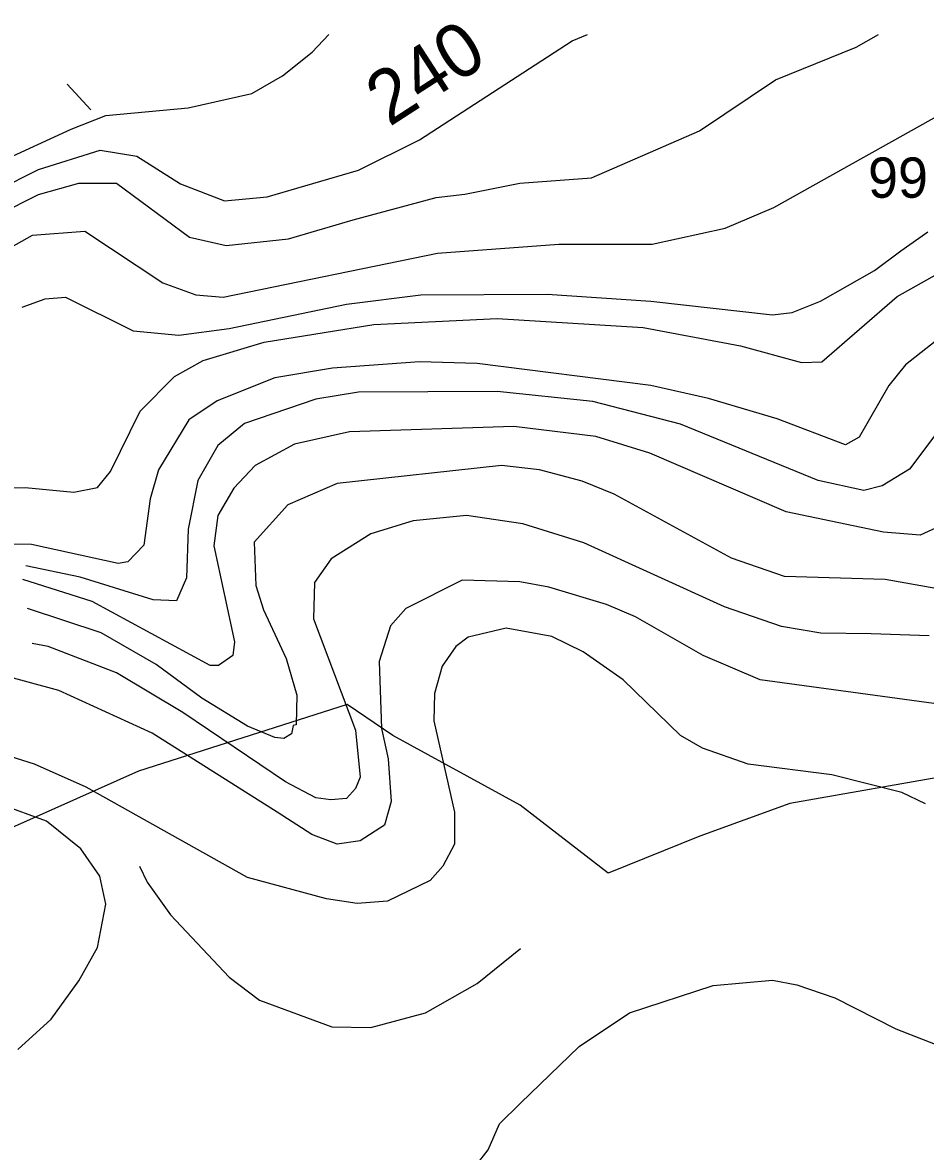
# Model space of a CAD drawing. Extents: x -662500 to -653478, y -1056827 to -1049993.
# Drawn here: x -661381.2 to -661213, y -1051221.5 to -1051011.2 of the extents above; entities that cross this region are included whole.
import ezdxf

# ---------------------------------------------------------------- set-up
doc = ezdxf.new("R2010")
doc.units = 0
doc.layers.add('Vrstva 24', color=7, linetype='Continuous')
doc.layers.add('Vrstva 7', color=7, linetype='Continuous')

msp = doc.modelspace()

# ---------------------------------------------------------------- linework, layer by layer
at = {"layer": 'Vrstva 24'}
msp.add_lwpolyline([(-661207.17, -1051151.19), (-661238.28, -1051156.7), (-661255.08, -1051162.76), (-661272.15, -1051169.64), (-661288.53, -1051156.97), (-661312.21, -1051144.03), (-661320.75, -1051138.25), (-661359.57, -1051150.64), (-661432.95, -1051183.41)], dxfattribs=at)
at = {"layer": 'Vrstva 7'}
for p, q in [((-661327.26, -1051016.72), (-661324.12, -1051013.4)), ((-661278.83, -1051014.6), (-661275.99, -1051013.4)), ((-661225.93, -1051015.73), (-661221.8, -1051013.4)), ((-661307.28, -1051033.02), (-661278.83, -1051014.6)), ((-661332.79, -1051021.12), (-661327.26, -1051016.72)), ((-661240.96, -1051021.83), (-661225.93, -1051015.73)), ((-661338.46, -1051024.38), (-661332.79, -1051021.12)), ((-661255.13, -1051031.32), (-661240.96, -1051021.83)), ((-661368.47, -1051027.44), (-661372.89, -1051022.68)), ((-661350.36, -1051027.07), (-661338.46, -1051024.38)), ((-661241.24, -1051045.63), (-661204.82, -1051025.23)), ((-661365.67, -1051028.51), (-661350.36, -1051027.07)), ((-661372.13, -1051031.03), (-661365.67, -1051028.51)), ((-661385.41, -1051037.13), (-661372.13, -1051031.03)), ((-661275.25, -1051040.11), (-661255.13, -1051031.32)), ((-661318.62, -1051038.69), (-661307.28, -1051033.02)), ((-661378.23, -1051038.56), (-661366.75, -1051034.98)), ((-661366.75, -1051034.98), (-661359.93, -1051036.05)), ((-661359.93, -1051036.05), (-661351.78, -1051041.24)), ((-661389.71, -1051044.31), (-661378.23, -1051038.56)), ((-661335.62, -1051043.65), (-661318.62, -1051038.69)), ((-661288.57, -1051041.1), (-661275.25, -1051040.11)), ((-661378.23, -1051043.23), (-661370.7, -1051041.08)), ((-661370.7, -1051041.08), (-661363.68, -1051041.1)), ((-661363.68, -1051041.1), (-661350.08, -1051051.16)), ((-661351.78, -1051041.24), (-661343.56, -1051044.36)), ((-661298.83, -1051043.16), (-661288.57, -1051041.1)), ((-661385.41, -1051046.82), (-661378.23, -1051043.23)), ((-661343.56, -1051044.36), (-661335.62, -1051043.65)), ((-661319.61, -1051047.9), (-661304.16, -1051043.79)), ((-661304.16, -1051043.79), (-661298.83, -1051043.16)), ((-661250.31, -1051049.46), (-661241.24, -1051045.63)), ((-661331.65, -1051051.45), (-661319.61, -1051047.9)), ((-661389, -1051056.15), (-661379.31, -1051050.77)), ((-661379.31, -1051050.77), (-661369.62, -1051050.05)), ((-661369.62, -1051050.05), (-661355.04, -1051059.66)), ((-661350.08, -1051051.16), (-661343.28, -1051052.72)), ((-661263.91, -1051052.44), (-661250.31, -1051049.46)), ((-661217.64, -1051053.69), (-661212.61, -1051050.17)), ((-661343.28, -1051052.72), (-661331.65, -1051051.45)), ((-661303.88, -1051054.14), (-661281.34, -1051052.44)), ((-661281.34, -1051052.44), (-661263.91, -1051052.44)), ((-661343.84, -1051062.36), (-661303.88, -1051054.14)), ((-661222.53, -1051057.4), (-661217.64, -1051053.69)), ((-661232.59, -1051063.07), (-661222.53, -1051057.4)), ((-661218.28, -1051062.22), (-661209.21, -1051057.11)), ((-661355.04, -1051059.66), (-661348.94, -1051061.93)), ((-661306.99, -1051061.93), (-661283.47, -1051061.79)), ((-661283.47, -1051061.79), (-661264.2, -1051063.06)), ((-661381.26, -1051064.2), (-661377, -1051062.64)), ((-661377, -1051062.64), (-661373.18, -1051062.36)), ((-661373.18, -1051062.36), (-661360.56, -1051068.59)), ((-661348.94, -1051061.93), (-661343.84, -1051062.36)), ((-661342.71, -1051068.17), (-661320.88, -1051063.63)), ((-661320.88, -1051063.63), (-661306.99, -1051061.93)), ((-661264.2, -1051063.06), (-661241.52, -1051065.62)), ((-661237.84, -1051065.19), (-661232.59, -1051063.07)), ((-661232.31, -1051074.4), (-661218.28, -1051062.22)), ((-661241.52, -1051065.62), (-661237.84, -1051065.19)), ((-661336.19, -1051070.72), (-661315.78, -1051067.46)), ((-661315.78, -1051067.46), (-661292.82, -1051066.32)), ((-661292.82, -1051066.32), (-661265.61, -1051068.02)), ((-661265.61, -1051068.02), (-661247.47, -1051071.43)), ((-661207.79, -1051067.88), (-661216.72, -1051074.97)), ((-661360.56, -1051068.59), (-661352.06, -1051069.44)), ((-661352.06, -1051069.44), (-661342.71, -1051068.17)), ((-661347.53, -1051074.12), (-661336.19, -1051070.72)), ((-661247.47, -1051071.43), (-661236.14, -1051074.54)), ((-661352.91, -1051077.09), (-661347.53, -1051074.12)), ((-661307.28, -1051074.4), (-661323.44, -1051075.54)), ((-661296.51, -1051074.69), (-661307.28, -1051074.4)), ((-661236.14, -1051074.54), (-661232.31, -1051074.4)), ((-661323.44, -1051075.54), (-661334.2, -1051077.38)), ((-661264.2, -1051078.8), (-661296.51, -1051074.69)), ((-661216.72, -1051074.97), (-661219.84, -1051078.8)), ((-661359.29, -1051083.61), (-661352.91, -1051077.09)), ((-661334.2, -1051077.38), (-661344.97, -1051081.63)), ((-661318.62, -1051080.07), (-661326.55, -1051081.35)), ((-661292.82, -1051079.93), (-661318.62, -1051080.07)), ((-661274.97, -1051081.77), (-661292.82, -1051079.93)), ((-661253.43, -1051081.21), (-661264.2, -1051078.8)), ((-661219.84, -1051078.8), (-661225.37, -1051088.43)), ((-661344.97, -1051081.63), (-661350.22, -1051085.17)), ((-661326.55, -1051081.35), (-661339.87, -1051085.88)), ((-661258.67, -1051086.02), (-661274.97, -1051081.77)), ((-661240.67, -1051085.03), (-661253.43, -1051081.21)), ((-661206.23, -1051081.35), (-661216.01, -1051094.38)), ((-661364.82, -1051094.81), (-661359.29, -1051083.61)), ((-661350.22, -1051085.17), (-661355.89, -1051094.53)), ((-661339.87, -1051085.88), (-661344.83, -1051089.99)), ((-661289.71, -1051086.45), (-661320.32, -1051087.44)), ((-661274.4, -1051088.29), (-661289.71, -1051086.45)), ((-661233.02, -1051096.51), (-661258.67, -1051086.02)), ((-661227.92, -1051089.85), (-661240.67, -1051085.03)), ((-661320.32, -1051087.44), (-661330.52, -1051089.71)), ((-661264.34, -1051091.41), (-661274.4, -1051088.29)), ((-661225.37, -1051088.43), (-661227.92, -1051089.85)), ((-661344.83, -1051089.99), (-661348.52, -1051096.51)), ((-661330.52, -1051089.71), (-661337.89, -1051093.68)), ((-661238.97, -1051102.32), (-661264.34, -1051091.41)), ((-661367.22, -1051097.79), (-661364.82, -1051094.81)), ((-661355.89, -1051094.53), (-661357.45, -1051099.91)), ((-661337.89, -1051093.68), (-661341.86, -1051097.93)), ((-661291.97, -1051093.68), (-661322.58, -1051097.08)), ((-661284.89, -1051094.53), (-661291.97, -1051093.68)), ((-661276.95, -1051096.65), (-661284.89, -1051094.53)), ((-661216.01, -1051094.38), (-661221.11, -1051097.5)), ((-661348.52, -1051096.51), (-661350.36, -1051105.58)), ((-661322.58, -1051097.08), (-661331.8, -1051101.04)), ((-661271, -1051099.06), (-661276.95, -1051096.65)), ((-661224.52, -1051098.35), (-661233.02, -1051096.51)), ((-661221.11, -1051097.5), (-661224.52, -1051098.35)), ((-661392.03, -1051097.93), (-661380.69, -1051097.79)), ((-661380.69, -1051097.79), (-661371.62, -1051098.64)), ((-661371.62, -1051098.64), (-661367.22, -1051097.79)), ((-661341.86, -1051097.93), (-661344.83, -1051103.03)), ((-661249.18, -1051110.97), (-661271, -1051099.06)), ((-661357.45, -1051099.91), (-661358.58, -1051108.56)), ((-661331.8, -1051101.04), (-661338.03, -1051107.99)), ((-661344.83, -1051103.03), (-661345.54, -1051108.7)), ((-661298.49, -1051103.03), (-661308.41, -1051104.02)), ((-661288.01, -1051104.59), (-661298.49, -1051103.03)), ((-661220.83, -1051106.15), (-661238.97, -1051102.32)), ((-661350.36, -1051105.58), (-661350.64, -1051114.65)), ((-661308.41, -1051104.02), (-661316.35, -1051106.43)), ((-661276.67, -1051108.13), (-661288.01, -1051104.59)), ((-661210.34, -1051105.01), (-661214.03, -1051106.71)), ((-661338.03, -1051107.99), (-661337.75, -1051116.07)), ((-661316.35, -1051106.43), (-661323.72, -1051111.11)), ((-661214.03, -1051106.71), (-661220.83, -1051106.15)), ((-661379.55, -1051108.42), (-661395.71, -1051108.27)), ((-661363.4, -1051111.96), (-661379.55, -1051108.42)), ((-661358.58, -1051108.56), (-661361.56, -1051111.67)), ((-661345.54, -1051108.7), (-661341.72, -1051126.55)), ((-661250.45, -1051120.03), (-661276.67, -1051108.13)), ((-661361.56, -1051111.67), (-661363.4, -1051111.96)), ((-661323.72, -1051111.11), (-661326.83, -1051115.5)), ((-661239.26, -1051114.37), (-661249.18, -1051110.97)), ((-661370.48, -1051114.51), (-661380.55, -1051112.38)), ((-661220.55, -1051114.93), (-661239.26, -1051114.37)), ((-661368.22, -1051119.04), (-661381.11, -1051114.93)), ((-661356.88, -1051118.76), (-661370.48, -1051114.51)), ((-661350.64, -1051114.65), (-661352.49, -1051118.9)), ((-661337.75, -1051116.07), (-661336.33, -1051120.6)), ((-661326.83, -1051115.5), (-661326.98, -1051122.3)), ((-661299.34, -1051115.07), (-661309.83, -1051120.32)), ((-661288.57, -1051115.36), (-661299.34, -1051115.07)), ((-661283.19, -1051116.35), (-661288.57, -1051115.36)), ((-661272.42, -1051119.61), (-661283.19, -1051116.35)), ((-661206.38, -1051117.49), (-661220.55, -1051114.93)), ((-661366.52, -1051124.85), (-661380.26, -1051120.32)), ((-661346.25, -1051130.95), (-661368.22, -1051119.04)), ((-661352.49, -1051118.9), (-661356.88, -1051118.76)), ((-661336.33, -1051120.6), (-661332.08, -1051129.67)), ((-661309.83, -1051120.32), (-661312.66, -1051123.58)), ((-661267.03, -1051121.88), (-661272.42, -1051119.61)), ((-661239.82, -1051123.72), (-661250.45, -1051120.03)), ((-661326.98, -1051122.3), (-661319.18, -1051142.99)), ((-661254.42, -1051129.1), (-661267.03, -1051121.88)), ((-661356.31, -1051130.81), (-661366.52, -1051124.85)), ((-661312.66, -1051123.58), (-661314.79, -1051130.24)), ((-661291.12, -1051124), (-661298.21, -1051125.7)), ((-661282.62, -1051125.56), (-661291.12, -1051124)), ((-661232.53, -1051124.97), (-661239.82, -1051123.72)), ((-661376.44, -1051127.41), (-661379.41, -1051126.84)), ((-661341.72, -1051126.55), (-661342, -1051129.1)), ((-661298.21, -1051125.7), (-661300.48, -1051127.41)), ((-661276.81, -1051128.4), (-661282.62, -1051125.56)), ((-661223.12, -1051125.08), (-661232.53, -1051124.97)), ((-661212.33, -1051125.42), (-661223.12, -1051125.08)), ((-661363.68, -1051132.36), (-661376.44, -1051127.41)), ((-661342, -1051129.1), (-661344.69, -1051130.95)), ((-661300.48, -1051127.41), (-661303.03, -1051131.09)), ((-661269.3, -1051133.64), (-661276.81, -1051128.4)), ((-661243.79, -1051133.64), (-661254.42, -1051129.1)), ((-661374.45, -1051135.62), (-661390.61, -1051131.23)), ((-661347.81, -1051137.04), (-661356.31, -1051130.81)), ((-661344.69, -1051130.95), (-661346.25, -1051130.95)), ((-661332.08, -1051129.67), (-661330.09, -1051136.48)), ((-661314.79, -1051130.24), (-661314.36, -1051142.71)), ((-661303.03, -1051131.09), (-661304.44, -1051136.19)), ((-661351.35, -1051139.73), (-661363.68, -1051132.36)), ((-661258.67, -1051143.99), (-661269.3, -1051133.64)), ((-661211.48, -1051138.03), (-661243.79, -1051133.64)), ((-661357.02, -1051143.56), (-661374.45, -1051135.62)), ((-661339.31, -1051142.28), (-661347.81, -1051137.04)), ((-661330.09, -1051136.48), (-661330.24, -1051142)), ((-661304.44, -1051136.19), (-661304.59, -1051141.29)), ((-661332.22, -1051152.63), (-661351.35, -1051139.73)), ((-661304.59, -1051141.29), (-661300.76, -1051158.3)), ((-661333.78, -1051158.3), (-661357.02, -1051143.56)), ((-661334.2, -1051144.41), (-661339.31, -1051142.28)), ((-661331.09, -1051143.7), (-661332.5, -1051144.55)), ((-661330.8, -1051142.14), (-661331.09, -1051143.7)), ((-661330.24, -1051142), (-661330.8, -1051142.14)), ((-661319.18, -1051142.99), (-661318.33, -1051151.78)), ((-661314.36, -1051142.71), (-661313.09, -1051148.38)), ((-661332.5, -1051144.55), (-661334.2, -1051144.41)), ((-661254.56, -1051146.4), (-661258.67, -1051143.99)), ((-661378.99, -1051149.37), (-661389.19, -1051146.11)), ((-661246.06, -1051149.37), (-661254.56, -1051146.4)), ((-661369.35, -1051153.62), (-661378.99, -1051149.37)), ((-661313.09, -1051148.38), (-661312.52, -1051156.31)), ((-661230.47, -1051151.35), (-661246.06, -1051149.37)), ((-661318.33, -1051151.78), (-661319.18, -1051153.91)), ((-661217.43, -1051154.61), (-661230.47, -1051151.35)), ((-661339.31, -1051170.49), (-661369.35, -1051153.62)), ((-661326.55, -1051155.61), (-661332.22, -1051152.63)), ((-661319.18, -1051153.91), (-661320.88, -1051155.75)), ((-661323.76, -1051156.02), (-661326.55, -1051155.61)), ((-661320.88, -1051155.75), (-661323.76, -1051156.02)), ((-661312.52, -1051156.31), (-661313.8, -1051160.71)), ((-661213.04, -1051156.74), (-661217.43, -1051154.61)), ((-661376.72, -1051160), (-661385.22, -1051156.88)), ((-661327.3, -1051162.43), (-661333.78, -1051158.3)), ((-661300.76, -1051158.3), (-661300.76, -1051164.25)), ((-661370.34, -1051165.1), (-661376.72, -1051160)), ((-661322.58, -1051164.25), (-661327.3, -1051162.43)), ((-661313.8, -1051160.71), (-661318.34, -1051163.64)), ((-661318.34, -1051163.64), (-661322.58, -1051164.25)), ((-661300.76, -1051164.25), (-661302.89, -1051168.36)), ((-661366.8, -1051170.2), (-661370.34, -1051165.1)), ((-661359.43, -1051168.36), (-661358.01, -1051171.34)), ((-661302.89, -1051168.36), (-661305.3, -1051171.05)), ((-661365.67, -1051175.45), (-661366.8, -1051170.2)), ((-661324.57, -1051174.46), (-661339.31, -1051170.49)), ((-661305.3, -1051171.05), (-661313.23, -1051174.88)), ((-661358.01, -1051171.34), (-661353.62, -1051177.43)), ((-661318.9, -1051175.3), (-661324.57, -1051174.46)), ((-661313.23, -1051174.88), (-661318.9, -1051175.3)), ((-661367.22, -1051183.52), (-661365.67, -1051175.45)), ((-661353.62, -1051177.43), (-661342.71, -1051189.05)), ((-661370.7, -1051189.69), (-661367.22, -1051183.52)), ((-661296.51, -1051190.19), (-661288.43, -1051183.67)), ((-661375.87, -1051196.85), (-661370.7, -1051189.69)), ((-661342.71, -1051189.05), (-661337.04, -1051193.3)), ((-661252.58, -1051190.61), (-661241.52, -1051189.62)), ((-661241.52, -1051189.62), (-661236.99, -1051190.47)), ((-661306.15, -1051195.71), (-661296.51, -1051190.19)), ((-661268.17, -1051195.71), (-661252.58, -1051190.61)), ((-661236.99, -1051190.47), (-661229.9, -1051192.88)), ((-661337.04, -1051193.3), (-661323.58, -1051198.26)), ((-661229.9, -1051192.88), (-661218.56, -1051198.69)), ((-661316.35, -1051198.4), (-661306.15, -1051195.71)), ((-661277.52, -1051201.95), (-661268.17, -1051195.71)), ((-661382.1, -1051202.51), (-661375.87, -1051196.85)), ((-661323.58, -1051198.26), (-661316.35, -1051198.4)), ((-661218.56, -1051198.69), (-661209.78, -1051202.09)), ((-661288.43, -1051212.52), (-661277.52, -1051201.95)), ((-661292.39, -1051216.34), (-661288.43, -1051212.52)), ((-661294.49, -1051221.19), (-661292.39, -1051216.34)), ((-661296.89, -1051224.32), (-661294.49, -1051221.19))]:
    msp.add_line(p, q, dxfattribs=at)

# ---------------------------------------------------------------- texts
at = {"layer": 'Vrstva 24'}
msp.add_text('99', height=7.5, dxfattribs=at).set_placement((-661223.72, -1051043.81))
at = {"layer": 'Vrstva 7'}
msp.add_text('240', height=10, rotation=32.9257, dxfattribs=at).set_placement((-661312.89, -1051030.7))

doc.saveas('drawing.dxf')
